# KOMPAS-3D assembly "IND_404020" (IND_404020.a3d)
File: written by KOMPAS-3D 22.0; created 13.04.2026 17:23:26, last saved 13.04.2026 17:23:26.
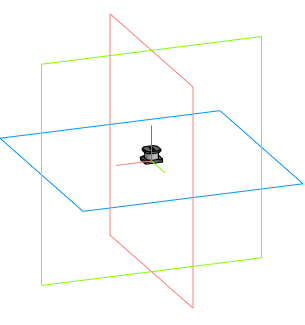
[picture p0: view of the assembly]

Document properties: Автор: Andrey; Полное имя файла: C:\Users\User1\Documents\IND_404020.a3d

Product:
- Component [assembly]: Part001  | qty 1  | source file: Part001.a3d
- Part/product: IND_404020
    Комментарий: IND_404020

Referenced files in C:\Users\User1\Documents\: Part001.a3d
